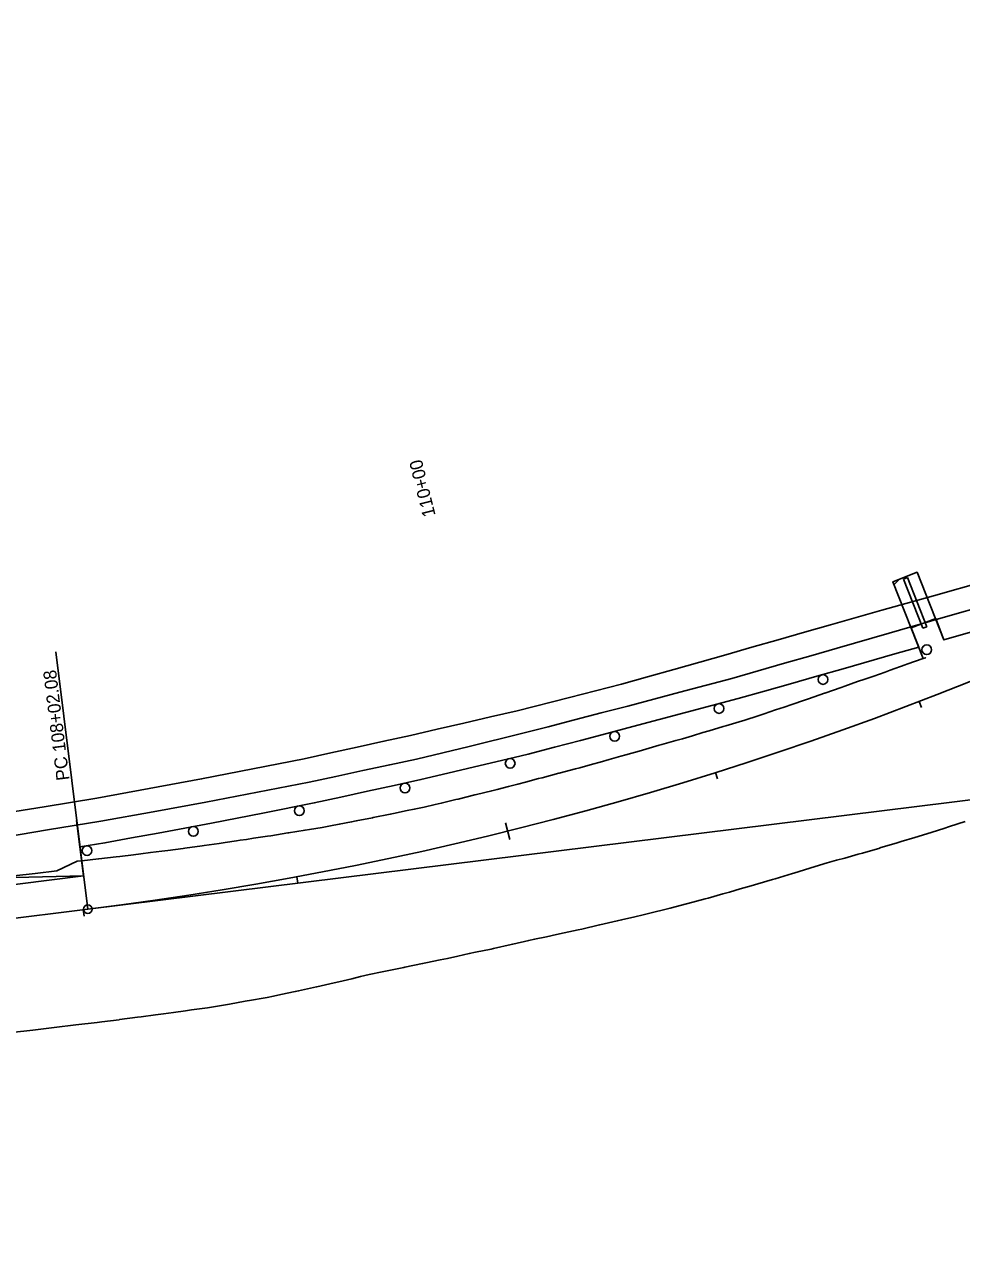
# Model space of a CAD drawing. Extents: x 1568809 to 1572786, y 728326 to 734907.
# Drawn here: x 1571053 to 1571487, y 732119 to 732690 of the extents above; entities that cross this region are included whole.
import ezdxf

# ---------------------------------------------------------------- set-up
doc = ezdxf.new("R2010")
doc.units = 0
for name, color, linetype in [('R_Horz Alg', 7, 'Continuous'), ('R_Horz Alg Annot', 7, 'Continuous'), ('R_MOT', 7, 'Continuous'), ('R_No Plot', 7, 'Continuous'), ('R_Proposed Const Limits_Fill', 7, 'Continuous'), ('R_Striping', 7, 'Continuous'), ('R_Water', 7, 'Continuous')]:
    doc.layers.add(name, color=color, linetype=linetype)

msp = doc.modelspace()

# ---------------------------------------------------------------- linework, layer by layer
at = {"layer": 'R_Horz Alg'}
msp.add_line((1569774.69, 732119.01), (1571082.41, 732280.73), dxfattribs=at)
msp.add_arc((1570881.49, 733905.38), 1637.02, 277.05, 312.07494, dxfattribs=at)
at = {"layer": 'R_Horz Alg Annot'}
msp.add_line((1571082.41, 732280.73), (1571595.05, 732344.13), dxfattribs=at)
for points in [[(1571082.41, 732280.73), (1571067.68, 732399.83)], [(1571468.61, 732374.05), (1571467.54, 732376.85)], [(1571374.03, 732341.07), (1571373.13, 732343.93)], [(1571275.93, 732320.71), (1571277.86, 732312.94)], [(1571179.72, 732292.7), (1571179.18, 732295.65)], [(1571080.72, 732277.5), (1571080.35, 732280.48)]]:
    msp.add_lwpolyline(points, dxfattribs=at)
msp.add_circle((1571082.41, 732280.73), 2, dxfattribs=at)
at = {"layer": 'R_MOT'}
msp.add_line((1571455.92, 732431.04), (1571458.35, 732433.48), dxfattribs=at)
for centre in [(1571471.02, 732400.82), (1571422.96, 732387.04), (1571374.82, 732373.62), (1571326.5, 732360.74), (1571278.06, 732348.21), (1571229.34, 732336.81), (1571180.43, 732326.27), (1571131.34, 732316.69), (1571082.09, 732307.83)]:
    msp.add_circle(centre, 2.25, dxfattribs=at)
at = {"layer": 'R_No Plot'}
for p in [(1571077.28, 732321.75), (1571078.82, 732309.53)]:
    msp.add_line(p, (1571080.52, 732296.05), dxfattribs=at)
for points in [[(1571469.37, 732396.77), (1571455.37, 732432.3), (1571466.53, 732436.7), (1571478.88, 732405.37), (1571492.28, 732409.3), (1571504.36, 732412.85), (1571516.43, 732416.4), (1571528.51, 732419.94), (1571540.52, 732423.79), (1571576.03, 732435.15)], [(1571576.03, 732435.15), (1571540.52, 732423.79), (1571528.51, 732419.94), (1571516.43, 732416.4), (1571504.36, 732412.85), (1571492.28, 732409.3), (1571478.88, 732405.37), (1571466.53, 732436.7), (1571455.37, 732432.3), (1571469.37, 732396.77)], [(1571492.28, 732409.3), (1571478.88, 732405.37), (1571475.14, 732415.24), (1571463.75, 732411.02), (1571467.29, 732402.04), (1571456.21, 732398.85), (1571432.22, 732391.94), (1571420.08, 732388.52), (1571407.95, 732385.1), (1571395.82, 732381.68), (1571383.68, 732378.26), (1571371.49, 732375.01), (1571359.3, 732371.75), (1571347.11, 732368.49), (1571334.93, 732365.24), (1571322.8, 732362.04), (1571310.67, 732358.84), (1571298.54, 732355.64), (1571286.41, 732352.44), (1571273.98, 732349.5), (1571261.55, 732346.56), (1571249.12, 732343.61), (1571236.69, 732340.67), (1571224.35, 732337.97), (1571212.01, 732335.27), (1571199.67, 732332.57), (1571187.33, 732329.87), (1571163.51, 732325.17), (1571139.68, 732320.46), (1571127.35, 732318.19), (1571115.01, 732315.92), (1571102.68, 732313.66), (1571090.34, 732311.39), (1571078.82, 732309.53)], [(1571048.18, 732296.13), (1571058.12, 732297.26), (1571068.06, 732298.4), (1571077.58, 732302.86), (1571079.65, 732303.08), (1571087.41, 732303.96), (1571087.62, 732303.98), (1571095.59, 732304.92), (1571097.21, 732305.11), (1571103.56, 732305.88), (1571107, 732306.31), (1571111.53, 732306.88), (1571116.79, 732307.54), (1571119.49, 732307.89), (1571126.57, 732308.84), (1571127.45, 732308.96), (1571135.4, 732310.05), (1571136.35, 732310.18), (1571143.35, 732311.17), (1571146.12, 732311.56), (1571151.3, 732312.32), (1571153.04, 732312.58), (1571155.89, 732313.01), (1571159.24, 732313.52), (1571165.66, 732314.44), (1571167.2, 732314.68), (1571175.13, 732315.97), (1571175.41, 732316.01), (1571183.05, 732317.29), (1571185.15, 732317.62), (1571190.99, 732318.57), (1571194.89, 732319.31), (1571198.89, 732320.04), (1571204.6, 732321.11), (1571206.78, 732321.53), (1571214.29, 732323.02), (1571214.67, 732323.09), (1571222.55, 732324.66), (1571223.98, 732324.96), (1571230.41, 732326.31), (1571233.65, 732326.99), (1571238.27, 732327.99), (1571243.29, 732329.13), (1571246.11, 732329.77), (1571252.9, 732331.44), (1571253.92, 732331.68), (1571261.74, 732333.56), (1571262.5, 732333.76), (1571269.53, 732335.51), (1571272.08, 732336.14), (1571277.32, 732337.52), (1571281.65, 732338.61), (1571285.11, 732339.49), (1571291.2, 732341.13), (1571292.87, 732341.57), (1571300.64, 732343.62), (1571300.75, 732343.65), (1571308.4, 732345.7), (1571310.29, 732346.21), (1571316.15, 732347.82), (1571319.82, 732348.83), (1571323.9, 732349.96), (1571329.33, 732351.48), (1571331.64, 732352.13), (1571338.83, 732354.19), (1571339.37, 732354.34), (1571347.09, 732356.57), (1571348.33, 732356.92), (1571354.83, 732358.75), (1571357.84, 732359.61), (1571362.55, 732360.99), (1571367.31, 732362.43), (1571370.25, 732363.31), (1571376.79, 732365.23), (1571377.96, 732365.58), (1571385.67, 732367.89), (1571386.25, 732368.08), (1571393.33, 732370.34), (1571395.65, 732371.16), (1571400.93, 732372.97), (1571405.02, 732374.3), (1571408.57, 732375.48), (1571414.36, 732377.52), (1571416.17, 732378.11), (1571423.7, 732380.76), (1571423.75, 732380.78), (1571431.38, 732383.34), (1571433.08, 732383.88), (1571438.95, 732386.05), (1571442.39, 732387.22), (1571446.57, 732388.65), (1571451.74, 732390.45), (1571454.13, 732391.4), (1571461.02, 732393.85), (1571461.71, 732394.09), (1571469.37, 732396.77)], [(1571469.37, 732396.77), (1571461.71, 732394.09), (1571461.02, 732393.85), (1571454.13, 732391.4), (1571451.74, 732390.45), (1571446.57, 732388.65), (1571442.39, 732387.22), (1571438.95, 732386.05), (1571433.08, 732383.88), (1571431.38, 732383.34), (1571423.75, 732380.78), (1571423.7, 732380.76), (1571416.17, 732378.11), (1571414.36, 732377.52), (1571408.57, 732375.48), (1571405.02, 732374.3), (1571400.93, 732372.97), (1571395.65, 732371.16), (1571393.33, 732370.34), (1571386.25, 732368.08), (1571385.67, 732367.89), (1571377.96, 732365.58), (1571376.79, 732365.23), (1571370.25, 732363.31), (1571367.31, 732362.43), (1571362.55, 732360.99), (1571357.84, 732359.61), (1571354.83, 732358.75), (1571348.33, 732356.92), (1571347.09, 732356.57), (1571339.37, 732354.34), (1571338.83, 732354.19), (1571331.64, 732352.13), (1571329.33, 732351.48), (1571323.9, 732349.96), (1571319.82, 732348.83), (1571316.15, 732347.82), (1571310.29, 732346.21), (1571308.4, 732345.7), (1571300.75, 732343.65), (1571300.64, 732343.62), (1571292.87, 732341.57), (1571291.2, 732341.13), (1571285.11, 732339.49), (1571281.65, 732338.61), (1571277.32, 732337.52), (1571272.08, 732336.14), (1571269.53, 732335.51), (1571262.5, 732333.76), (1571261.74, 732333.56), (1571253.92, 732331.68), (1571252.9, 732331.44), (1571246.11, 732329.77), (1571243.29, 732329.13), (1571238.27, 732327.99), (1571233.65, 732326.99), (1571230.41, 732326.31), (1571223.98, 732324.96), (1571222.55, 732324.66), (1571214.67, 732323.09), (1571214.29, 732323.02), (1571206.78, 732321.53), (1571204.6, 732321.11), (1571198.89, 732320.04), (1571194.89, 732319.31), (1571190.99, 732318.57), (1571185.15, 732317.62), (1571183.05, 732317.29), (1571175.41, 732316.01), (1571175.13, 732315.97), (1571167.2, 732314.68), (1571165.66, 732314.44), (1571159.24, 732313.52), (1571155.89, 732313.01), (1571153.04, 732312.58), (1571151.3, 732312.32), (1571146.12, 732311.56), (1571143.35, 732311.17), (1571136.35, 732310.18), (1571135.4, 732310.05), (1571127.45, 732308.96), (1571126.57, 732308.84), (1571119.49, 732307.89), (1571116.79, 732307.54), (1571111.53, 732306.88), (1571107, 732306.31), (1571103.56, 732305.88), (1571097.21, 732305.11), (1571095.59, 732304.92), (1571087.62, 732303.98), (1571087.41, 732303.96), (1571079.65, 732303.08), (1571077.58, 732302.86), (1571068.06, 732298.4), (1571058.12, 732297.26), (1571048.18, 732296.13)], [(1571488.83, 732321.34), (1571481.52, 732318.96), (1571478.96, 732318.12), (1571473.49, 732316.39), (1571469.07, 732315.01), (1571465.43, 732313.88), (1571459.15, 732311.97), (1571457.36, 732311.43), (1571449.27, 732309.03), (1571449.22, 732309.01), (1571441.18, 732306.67), (1571439.26, 732306.13), (1571433.06, 732304.38), (1571429.28, 732303.33), (1571424.94, 732302.14), (1571419.32, 732300.5), (1571416.87, 732299.72), (1571409.46, 732297.39), (1571408.85, 732297.2), (1571400.8, 732294.77), (1571399.57, 732294.39), (1571392.74, 732292.36), (1571389.66, 732291.45), (1571384.65, 732290.05), (1571379.71, 732288.63), (1571376.56, 732287.74), (1571369.75, 732285.85), (1571368.44, 732285.55), (1571360.32, 732283.35), (1571359.76, 732283.2), (1571352.19, 732281.2), (1571349.77, 732280.57), (1571344.04, 732279.16), (1571339.73, 732278.11), (1571335.86, 732277.19), (1571329.68, 732275.7), (1571327.69, 732275.23), (1571319.61, 732273.39), (1571319.49, 732273.36), (1571311.3, 732271.5), (1571309.54, 732271.11), (1571303.09, 732269.71), (1571299.45, 732268.89), (1571294.89, 732267.91), (1571289.36, 732266.75), (1571286.67, 732266.19), (1571279.28, 732264.53), (1571278.48, 732264.34), (1571270.3, 732262.46), (1571269.23, 732262.21), (1571262.08, 732260.78), (1571259.13, 732260.11), (1571253.89, 732258.95), (1571249.06, 732257.89), (1571245.68, 732257.23), (1571238.97, 732255.78), (1571237.48, 732255.46), (1571229.26, 732253.79), (1571228.87, 732253.71), (1571221.05, 732252.08), (1571218.77, 732251.61), (1571212.83, 732250.4), (1571208.69, 732249.45), (1571204.66, 732248.47), (1571198.66, 732247.03), (1571196.49, 732246.51), (1571188.58, 732244.79), (1571188.29, 732244.72), (1571180.1, 732242.85), (1571178.51, 732242.49), (1571171.86, 732241.2), (1571168.39, 732240.44), (1571165.45, 732239.8), (1571163.64, 732239.46), (1571158.25, 732238.51), (1571155.36, 732238.08), (1571148.08, 732236.77), (1571147.09, 732236.59), (1571138.81, 732235.2), (1571137.9, 732235.07), (1571130.5, 732234.01), (1571127.68, 732233.58), (1571122.18, 732232.83), (1571117.45, 732232.2), (1571113.86, 732231.73), (1571107.22, 732230.86), (1571105.53, 732230.62), (1571097.2, 732229.55), (1571096.98, 732229.52), (1571088.87, 732228.49), (1571086.81, 732228.24), (1571076.87, 732227.1), (1571066.94, 732225.91), (1571057.02, 732224.69), (1571047.08, 732223.57)], [(1571047.08, 732223.57), (1571057.02, 732224.69), (1571066.94, 732225.91), (1571076.87, 732227.1), (1571086.81, 732228.24), (1571088.87, 732228.49), (1571096.98, 732229.52), (1571097.2, 732229.55), (1571105.53, 732230.62), (1571107.22, 732230.86), (1571113.86, 732231.73), (1571117.45, 732232.2), (1571122.18, 732232.83), (1571127.68, 732233.58), (1571130.5, 732234.01), (1571137.9, 732235.07), (1571138.81, 732235.2), (1571147.09, 732236.59), (1571148.08, 732236.77), (1571155.36, 732238.08), (1571158.25, 732238.51), (1571163.64, 732239.46), (1571165.45, 732239.8), (1571168.39, 732240.44), (1571171.86, 732241.2), (1571178.51, 732242.49), (1571180.1, 732242.85), (1571188.29, 732244.72), (1571188.58, 732244.79), (1571196.49, 732246.51), (1571198.66, 732247.03), (1571204.66, 732248.47), (1571208.69, 732249.45), (1571212.83, 732250.4), (1571218.77, 732251.61), (1571221.05, 732252.08), (1571228.87, 732253.71), (1571229.26, 732253.79), (1571237.48, 732255.46), (1571238.97, 732255.78), (1571245.68, 732257.23), (1571249.06, 732257.89), (1571253.89, 732258.95), (1571259.13, 732260.11), (1571262.08, 732260.78), (1571269.23, 732262.21), (1571270.3, 732262.46), (1571278.48, 732264.34), (1571279.28, 732264.53), (1571286.67, 732266.19), (1571289.36, 732266.75), (1571294.89, 732267.91), (1571299.45, 732268.89), (1571303.09, 732269.71), (1571309.54, 732271.11), (1571311.3, 732271.5), (1571319.49, 732273.36), (1571319.61, 732273.39), (1571327.69, 732275.23), (1571329.68, 732275.7), (1571335.86, 732277.19), (1571339.73, 732278.11), (1571344.04, 732279.16), (1571349.77, 732280.57), (1571352.19, 732281.2), (1571359.76, 732283.2), (1571360.32, 732283.35), (1571368.44, 732285.55), (1571369.75, 732285.85), (1571376.56, 732287.74), (1571379.71, 732288.63), (1571384.65, 732290.05), (1571389.66, 732291.45), (1571392.74, 732292.36), (1571399.57, 732294.39), (1571400.8, 732294.77), (1571408.85, 732297.2), (1571409.46, 732297.39), (1571416.87, 732299.72), (1571419.32, 732300.5), (1571424.94, 732302.14), (1571429.28, 732303.33), (1571433.06, 732304.38), (1571439.26, 732306.13), (1571441.18, 732306.67), (1571449.22, 732309.01), (1571449.27, 732309.03), (1571457.36, 732311.43), (1571459.15, 732311.97), (1571465.43, 732313.88), (1571469.07, 732315.01), (1571473.49, 732316.39), (1571478.96, 732318.12), (1571481.52, 732318.96), (1571488.83, 732321.34)], [(1571080.52, 732296.05), (1570444.72, 732215.92), (1570431.22, 732213.94), (1570302.77, 732199.43)], [(1571080.52, 732296.05), (1570973.02, 732293.44), (1570943.63, 732289.39), (1570933.75, 732279.73), (1570896.54, 732272.86), (1570444.72, 732215.92), (1570431.22, 732213.94), (1570302.77, 732199.43)]]:
    msp.add_lwpolyline(points, dxfattribs=at)
at = {"layer": 'R_Proposed Const Limits_Fill'}
msp.add_lwpolyline([(1571048.18, 732296.13), (1571058.12, 732297.26), (1571068.06, 732298.4), (1571077.58, 732302.86), (1571077.58, 732302.86), (1571079.65, 732303.08), (1571087.41, 732303.96), (1571087.62, 732303.98), (1571095.59, 732304.92), (1571097.21, 732305.11), (1571103.56, 732305.88), (1571107, 732306.31), (1571111.53, 732306.88), (1571116.79, 732307.54), (1571119.49, 732307.89), (1571126.57, 732308.84), (1571127.45, 732308.96), (1571135.4, 732310.05), (1571136.35, 732310.18), (1571143.35, 732311.17), (1571146.12, 732311.56), (1571151.3, 732312.32), (1571153.04, 732312.58), (1571155.89, 732313.01), (1571159.24, 732313.52), (1571165.66, 732314.44), (1571167.2, 732314.68), (1571175.13, 732315.97), (1571175.41, 732316.01), (1571183.05, 732317.29), (1571185.15, 732317.62), (1571190.99, 732318.57), (1571194.89, 732319.31), (1571198.89, 732320.04), (1571204.6, 732321.11), (1571206.78, 732321.53), (1571214.29, 732323.02), (1571214.67, 732323.09), (1571222.55, 732324.66), (1571223.98, 732324.96), (1571230.41, 732326.31), (1571233.65, 732326.99), (1571238.27, 732327.99), (1571243.29, 732329.13), (1571246.11, 732329.77), (1571252.9, 732331.44), (1571253.92, 732331.68), (1571261.74, 732333.56), (1571262.5, 732333.76), (1571269.53, 732335.51), (1571272.08, 732336.14), (1571277.32, 732337.52), (1571281.65, 732338.61), (1571285.11, 732339.49), (1571291.2, 732341.13), (1571292.87, 732341.57), (1571300.64, 732343.62), (1571300.75, 732343.65), (1571308.4, 732345.7), (1571310.29, 732346.21), (1571316.15, 732347.82), (1571319.82, 732348.83), (1571323.9, 732349.96), (1571329.33, 732351.48), (1571331.64, 732352.13), (1571338.83, 732354.19), (1571339.37, 732354.34), (1571347.09, 732356.57), (1571348.33, 732356.92), (1571354.83, 732358.75), (1571357.84, 732359.61), (1571362.55, 732360.99), (1571367.31, 732362.43), (1571370.25, 732363.31), (1571376.79, 732365.23), (1571377.96, 732365.58), (1571385.67, 732367.89), (1571386.25, 732368.08), (1571393.33, 732370.34), (1571395.65, 732371.16), (1571400.93, 732372.97), (1571405.02, 732374.3), (1571408.57, 732375.48), (1571414.36, 732377.52), (1571416.17, 732378.11), (1571423.7, 732380.76), (1571423.75, 732380.78), (1571431.38, 732383.34), (1571433.08, 732383.88), (1571438.95, 732386.05), (1571442.39, 732387.22), (1571446.57, 732388.65), (1571451.74, 732390.45), (1571454.13, 732391.4), (1571461.02, 732393.85), (1571461.71, 732394.09), (1571469.31, 732396.75), (1571470.38, 732397.08), (1571470.63, 732397.16)], dxfattribs=at)
at = {"layer": 'R_Striping'}
for points in [[(1571037.88, 732324.21), (1571062.21, 732328.15), (1571086.55, 732332.08), (1571110.84, 732336.56), (1571135.14, 732341.04), (1571158.87, 732345.69), (1571182.6, 732350.35), (1571194.93, 732353.04), (1571207.26, 732355.74), (1571219.6, 732358.44), (1571231.93, 732361.14), (1571244.27, 732363.99), (1571256.61, 732366.84), (1571268.95, 732369.68), (1571281.29, 732372.53), (1571305.48, 732378.73), (1571329.66, 732384.93), (1571341.72, 732388.33), (1571353.79, 732391.73), (1571365.85, 732395.13), (1571377.91, 732398.54), (1571390.05, 732402), (1571402.2, 732405.45), (1571414.34, 732408.91), (1571426.49, 732412.37), (1571450.27, 732419.1), (1571474.06, 732425.84), (1571498, 732432.64)], [(1571039.19, 732313.32), (1571063.81, 732317.37), (1571088.43, 732321.42), (1571112.74, 732325.82), (1571137.05, 732330.22), (1571160.97, 732334.85), (1571184.9, 732339.47), (1571197.35, 732342.15), (1571209.81, 732344.84), (1571222.27, 732347.53), (1571234.72, 732350.21), (1571259, 732356.09), (1571283.28, 732361.98), (1571295.61, 732365.17), (1571307.93, 732368.35), (1571320.25, 732371.54), (1571332.57, 732374.73), (1571356.61, 732381.15), (1571380.66, 732387.57), (1571392.88, 732391.05), (1571405.11, 732394.53), (1571417.33, 732398.01), (1571429.55, 732401.48), (1571453.54, 732408.44), (1571477.54, 732415.39), (1571501.52, 732422.28)]]:
    msp.add_lwpolyline(points, dxfattribs=at)
at = {"layer": 'R_Water'}
for p, q in [((1571460.28, 732433.49), (1571462.14, 732434.22)), ((1571460.28, 732433.49), (1571469.23, 732410.76)), ((1571462.14, 732434.22), (1571471.09, 732411.5)), ((1571469.23, 732410.76), (1571471.09, 732411.5))]:
    msp.add_line(p, q, dxfattribs=at)

# ---------------------------------------------------------------- texts
at = {"layer": 'R_Horz Alg Annot'}
for s, rotation, p in [('110+00', 103.9773, (1571243.57, 732463.11)), ('PC 108+02.08', 97.05, (1571074, 732340.63))]:
    msp.add_text(s, height=6, rotation=rotation, dxfattribs=at).set_placement(p)

doc.saveas('drawing.dxf')
